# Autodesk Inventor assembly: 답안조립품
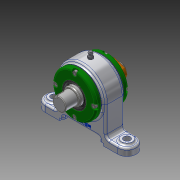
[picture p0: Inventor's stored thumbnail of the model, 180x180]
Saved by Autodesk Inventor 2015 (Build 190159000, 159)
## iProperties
Created: 2019-05
Part Number: 답안조립품
Document SubType Name: Assembly
Designer: now
Author: now
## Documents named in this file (13)
- C:\Users\now\Desktop\490504V1037\답안조립품.iam
- C:\Users\now\Desktop\490504V1037\개스킷.ipt
- C:\Users\now\Desktop\490504V1037\그리스니플 M6.ipt
- 그리스니플  M6.ipt
- C:\Users\now\Desktop\490504V1037\그리스니플개스킷.ipt
- C:\Users\now\Desktop\490504V1037\베어링너트.ipt
- C:\Users\now\Desktop\490504V1037\본체.ipt
- C:\Users\now\Desktop\490504V1037\볼트 M4.ipt
- C:\Users\now\Desktop\490504V1037\앵귤러 볼 베어링 7205.ipt
- C:\Users\now\Desktop\490504V1037\오일 실 28 40 5 B.ipt
- C:\Users\now\Desktop\490504V1037\축.ipt
- C:\Users\now\Desktop\490504V1037\칼라.ipt
- C:\Users\now\Desktop\490504V1037\커버.ipt
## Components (4 placed, 3 different names)
1. 개스킷:1
2. 그리스니플  M6:1
3. 그리스니플개스킷:1
4. 개스킷:2
